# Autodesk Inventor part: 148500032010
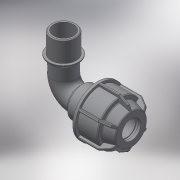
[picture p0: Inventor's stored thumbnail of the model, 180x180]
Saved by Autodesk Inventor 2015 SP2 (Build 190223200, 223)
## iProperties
Created: 2017-08
Part Number: 148500032010
Material: Generic
Description: PLASSON L.14 90° ELBOW MALE ADAPTOR (SILVER) 32-1"
Document SubType Name: Modeling
Designer: KIM
Density: 1 g/cm^3
Appearance: Default
Author: KIM
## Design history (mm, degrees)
derived "148500.ipt"
feature "Solid1::148500.ipt"
feature "Solid2::148500.ipt"
tag "TaggingFeature1"
body "Solid1"
body "Solid2"
other parameters: "d1" = 32, "d2" = 56, "d4" = 15 deg, "d5" = 36.96, "d6" = 12.1968, "d10" = 61, "d16" = 32.64, "d17" = 2.8, "d22" = 51.2, "d24" = 2.8, "d25" = 54.9, "d26" = 45.75, "d27" = 2.8, "d28" = 135 deg, "d29" = 1.68, "d31" = 1.6, "d46" = 150 deg, "d49" = 3.05, "d50" = 0, "d58" = 0.96, "d61" = 360 deg, "d63" = 28.8, "d94" = 53, "d96" = 36.5739, "d98" = 26.5992, "d99" = 31.08782, "d100" = 135 deg, "d108" = 1.6, "d112" = 26, "d113" = 75, "d114" = 57.12, "d115" = 31.08782, "d116" = 45 deg, "d117" = 0, "d118" = 0, "d119" = 33.249, "d121" = 39.8988, "d122" = 21, "d123" = 1, "d_" = 32, "R_" = 33.249, "E_" = 61, "A_" = 75, "l_" = 56, "A_1" = 53
